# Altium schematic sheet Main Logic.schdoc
size 517 x 342 mm
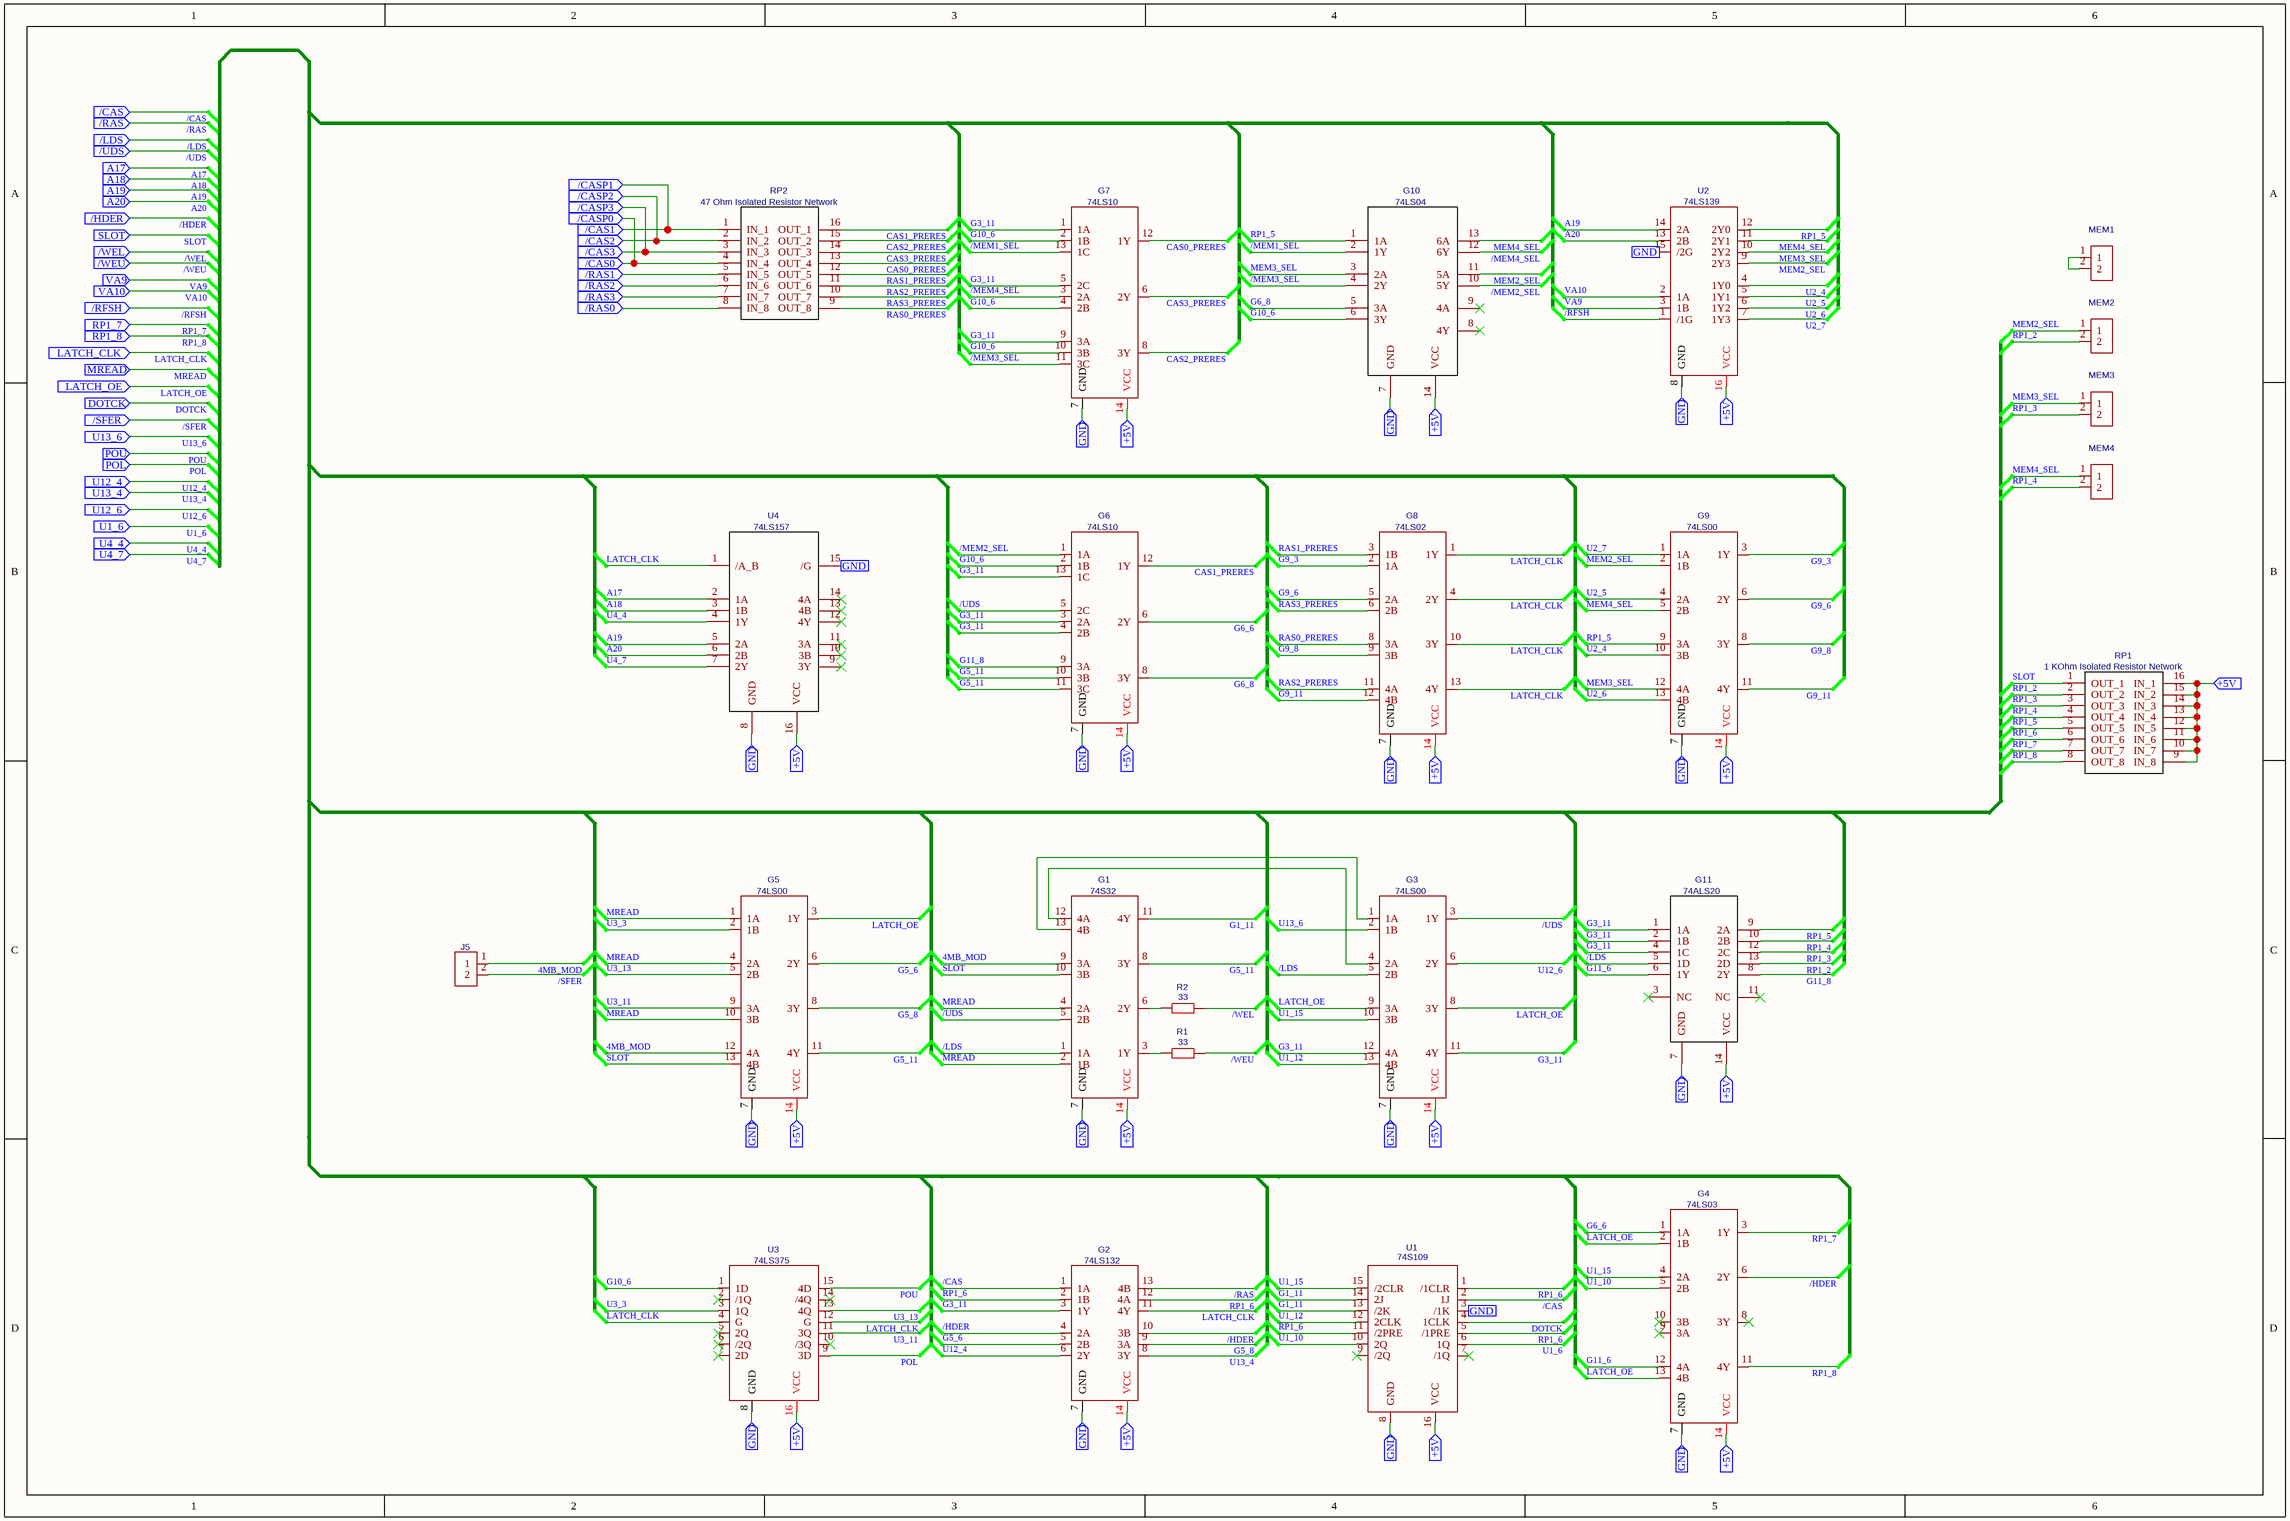
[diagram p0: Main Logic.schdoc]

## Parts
G1  74S32  [DIP-14_L19.4-W6.4-P2.54-LS7.6-BL]
G2  74LS132  [DIP-14_L19.2-W6.6-P2.54-LS10.9-BL]
G3  74LS00  [DIP14]
G4  74LS03  [DIP-14_L19.2-W6.6-P2.54-LS10.9-BL]
G5  74LS00  [DIP14]
G6  74LS10  [DIP14]
G7  74LS10  [DIP14]
G8  74LS02  [DIP-14_L19.4-W6.4-P2.54-LS7.6-BL]
G9  74LS00  [DIP14]
G10  74LS04  [DIP-14_L19.4-W6.4-P2.54-LS7.6-BL]
G11  74ALS20  [DIP-14_L19.4-W6.4-P2.54-LS7.6-BL]
J5  JUMPER2  [HDR-TH_2P-P2.54-V-M-1]  (value not drawn)
MEM1  MEM1  [HDR-TH_2P-P2.54-V-M-1]  (value not drawn)
MEM2  MEM2  [HDR-TH_2P-P2.54-V-M-1]  (value not drawn)
MEM3  MEM3  [HDR-TH_2P-P2.54-V-M-1]  (value not drawn)
MEM4  MEM4  [HDR-TH_2P-P2.54-V-M-1]  (value not drawn)
R1  33  [NARROW_RESISTOR]
R2  33  [NARROW_RESISTOR]
RP1  1 KOhm Isolated Resistor Network  [DIP-16_L19.7-W6.6-P2.54-LS7.6-BL]
RP2  47 Ohm Isolated Resistor Network  [DIP-16_L19.7-W6.6-P2.54-LS7.6-BL]
U1  74S109 (LISA)  [DIP-16_L19.7-W6.6-P2.54-LS7.6-BL]  (value not drawn)
U2  74LS139  [DIP-16_L19.7-W6.6-P2.54-LS7.6-BL]
U3  74LS375  [DIP-16_L19.7-W6.6-P2.54-LS7.6-BL]
U4  74LS157  [DIP-16_L19.7-W6.6-P2.54-LS7.6-BL]

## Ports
+5V (in), /CAS0 (in), /CAS1 (in), /CAS2 (in), /CAS3 (in), /CAS (in), /CASP0 (in), /CASP1 (in), /CASP2 (in), /CASP3 (in), /HDER (in), /LDS (in), /RAS0 (in), /RAS1 (in), /RAS2 (in), /RAS3 (in), /RAS (in), /RFSH (in), /SFER (in), /UDS (in), /WEL (in), /WEU (in), A17 (in), A18 (in), A19 (in), A20 (in), DOTCK (in), GND (in), LATCH_CLK (in), LATCH_OE (in), MREAD (in), POL (in), POU (in), RP1_7 (in), RP1_8 (in), SLOT (in), U1_6 (in), U4_4 (in), U4_7 (in), U12_4 (in), U12_6 (in), U13_4 (in), U13_6 (in), VA9 (in), VA10 (in)

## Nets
4MB_MOD: G1.9(3A) G5.12(4A) J5.1
+5V: G1.14(VCC) G2.14(VCC) G3.14(VCC) G4.14(VCC) G5.14(VCC) G6.14(VCC) G7.14(VCC) G8.14(VCC) G9.14(VCC) G10.14(VCC) G11.14(VCC) RP1.9(IN_8) RP1.10(IN_7) RP1.11(IN_6) RP1.12(IN_5) RP1.13(IN_4) RP1.14(IN_3) RP1.15(IN_2) RP1.16(IN_1) U1.16(VCC) U2.16(VCC) U3.16(VCC) U4.16(VCC) ; port +5V
/CAS: G2.1(1A) U1.2(1J) ; port /CAS
/CAS0: RP2.4(IN_4) ; port /CAS0, port /CASP0
/CAS1: RP2.1(IN_1) ; port /CAS1, port /CASP1
/CAS2: RP2.2(IN_2) ; port /CAS2, port /CASP2
/CAS3: RP2.3(IN_3) ; port /CAS3, port /CASP3
/HDER: G2.4(2A) G2.10(3B) G4.6(2Y) ; port /HDER
/LDS: G1.1(1A) G3.5(2B) G11.5(1D) ; port /LDS
/MEM1_SEL: G7.13(1C) G10.2(1Y)
/MEM2_SEL: G6.1(1A) G10.10(5Y)
/MEM3_SEL: G7.11(3C) G10.4(2Y)
/MEM4_SEL: G7.3(2A) G10.12(6Y)
/RAS: G2.13(4B) ; port /RAS
/RAS0: RP2.8(IN_8) ; port /RAS0
/RAS1: RP2.5(IN_5) ; port /RAS1
/RAS2: RP2.6(IN_6) ; port /RAS2
/RAS3: RP2.7(IN_7) ; port /RAS3
/RFSH: U2.1(/1G) ; port /RFSH
/SFER: J5.2 ; port /SFER
/UDS: G1.5(2B) G3.3(1Y) G6.5(2C) ; port /UDS
/WEL: R2.1 ; port /WEL
/WEU: R1.1 ; port /WEU
A17: U4.2(1A) ; port A17
A18: U4.3(1B) ; port A18
A19: U2.14(2A) U4.5(2A) ; port A19
A20: U2.13(2B) U4.6(2B) ; port A20
CAS0_PRERES: G7.12(1Y) RP2.13(OUT_4)
CAS1_PRERES: G6.12(1Y) RP2.16(OUT_1)
CAS2_PRERES: G7.8(3Y) RP2.15(OUT_2)
CAS3_PRERES: G7.6(2Y) RP2.14(OUT_3)
DOTCK: U1.4(1CLK) ; port DOTCK
G1_11: G1.11(4Y) U1.13(/2K) U1.14(2J)
G3_11: G2.3(1Y) G3.11(4Y) G3.12(4A) G6.3(2A) G6.4(2B) G6.13(1C) G7.1(1A) G7.5(2C) G7.9(3A) G11.1(1A) G11.2(1B) G11.4(1C)
G5_6: G2.5(2B) G5.6(2Y)
G5_8: G2.9(3A) G5.8(3Y)
G5_11: G1.8(3Y) G5.11(4Y) G6.10(3B) G6.11(3C)
G6_6: G4.1(1A) G6.6(2Y)
G6_8: G6.8(3Y) G10.5(3A)
G9_3: G8.2(1A) G9.3(1Y)
G9_6: G8.5(2A) G9.6(2Y)
G9_8: G8.9(3B) G9.8(3Y)
G9_11: G8.12(4B) G9.11(4Y)
G10_6: G6.2(1B) G7.2(1B) G7.4(2B) G7.10(3B) G10.6(3Y) U3.1(1D)
G11_6: G4.12(4A) G11.6(1Y)
G11_8: G6.9(3A) G11.8(2Y)
GND: G1.7(GND) G2.7(GND) G3.7(GND) G4.7(GND) G5.7(GND) G6.7(GND) G7.7(GND) G8.7(GND) G9.7(GND) G10.7(GND) G11.7(GND) U1.3(/1K) U1.8(GND) U2.8(GND) U2.15(/2G) U3.8(GND) U4.8(GND) U4.15(/G) ; port GND
LATCH_CLK: G2.11(4Y) G8.1(1Y) G8.4(2Y) G8.10(3Y) G8.13(4Y) U3.4(G) U3.12(G) U4.1(/A_B) ; port LATCH_CLK
LATCH_OE: G3.8(3Y) G3.9(3A) G4.2(1B) G4.13(4B) G5.3(1Y) ; port LATCH_OE
MEM2_SEL: G9.2(1B) G10.11(5A) MEM2.1 U2.9(2Y3)
MEM3_SEL: G9.12(4A) G10.3(2A) MEM3.1 U2.10(2Y2)
MEM4_SEL: G9.5(2B) G10.13(6A) MEM4.1 U2.11(2Y1)
MREAD: G1.2(1B) G1.4(2A) G5.1(1A) G5.4(2A) G5.10(3B) ; port MREAD
POL: U3.9(3D) ; port POL
POU: U3.15(4D) ; port POU
RAS0_PRERES: G8.8(3A) RP2.9(OUT_8)
RAS1_PRERES: G8.3(1B) RP2.12(OUT_5)
RAS2_PRERES: G8.11(4A) RP2.11(OUT_6)
RAS3_PRERES: G8.6(2B) RP2.10(OUT_7)
RP1_2: G11.13(2D) MEM2.2 RP1.2(OUT_2)
RP1_3: G11.12(2C) MEM3.2 RP1.3(OUT_3)
RP1_4: G11.10(2B) MEM4.2 RP1.4(OUT_4)
RP1_5: G9.9(3A) G10.1(1A) G11.9(2A) RP1.5(OUT_5) U2.12(2Y0)
RP1_6: G2.2(1B) G2.12(4A) RP1.6(OUT_6) U1.1(/1CLR) U1.5(/1PRE) U1.11(/2PRE)
RP1_7: G4.3(1Y) RP1.7(OUT_7) ; port RP1_7
RP1_8: G4.11(4Y) RP1.8(OUT_8) ; port RP1_8
SLOT: G1.10(3B) G5.13(4B) RP1.1(OUT_1) ; port SLOT
U1_6: U1.6(1Q) ; port U1_6
U1_10: G4.5(2B) U1.10(2Q)
U1_12: G3.13(4B) U1.12(2CLK)
U1_15: G3.10(3B) G4.4(2A) U1.15(/2CLR)
U2_4: G9.10(3B) U2.4(1Y0)
U2_5: G9.4(2A) U2.5(1Y1)
U2_6: G9.13(4B) U2.6(1Y2)
U2_7: G9.1(1A) U2.7(1Y3)
U3_3: G5.2(1B) U3.3(1Q)
U3_11: G5.9(3A) U3.11(3Q)
U3_13: G5.5(2B) U3.13(4Q)
U4_4: U4.4(1Y) ; port U4_4
U4_7: U4.7(2Y) ; port U4_7
U12_4: G2.6(2Y) ; port U12_4
U12_6: G3.6(2Y) ; port U12_6
U13_4: G2.8(3Y) ; port U13_4
U13_6: G3.2(1B) ; port U13_6
VA9: U2.3(1B) ; port VA9
VA10: U2.2(1A) ; port VA10
NetG1_3: G1.3(1Y) R1.2
NetG1_6: G1.6(2Y) R2.2
NetG1_12: G1.12(4A) G3.4(2A)
NetG1_13: G1.13(4B) G3.1(1A)
NetMEM1_1: MEM1.1 MEM1.2

Not connected (* = marked no-connect by the designer): G4 8(3Y)* 9(3A)* 10(3B)*; G10 8(4Y)* 9(4A)*; G11 3(NC)* 11(NC)*; U1 7(/1Q)* 9(/2Q)*; U3 2(/1Q)* 5(2Q)* 6(/2Q)* 7(2D)* 10(/3Q)* 14(/4Q)*; U4 9(3Y)* 10(3B)* 11(3A)* 12(4Y)* 13(4B)* 14(4A)*

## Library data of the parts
G1 = 74S32: Contributor: will_tooker
G2 = 74LS132: Contributor: will_tooker
G3 G5 G9 = 74LS00: Contributor: will_tooker
G4 = 74LS03: Contributor: William Tooker
G6 G7 = 74LS10: Contributor: will_tooker
G8 = 74LS02: Contributor: will_tooker
G10 = 74LS04: Contributor: William Tooker
G11 = 74ALS20: Contributor: will_tooker
J5 = JUMPER2: Manufacturer: null; Contributor: William Tooker
MEM1 = MEM1: Manufacturer: null; Manufacturer Part: Jumper2; Contributor: William Tooker
MEM2 = MEM2: Manufacturer: null; Manufacturer Part: Jumper2; Contributor: William Tooker
MEM3 = MEM3: Manufacturer: null; Manufacturer Part: Jumper2; Contributor: William Tooker
MEM4 = MEM4: Manufacturer: null; Manufacturer Part: Jumper2; Contributor: William Tooker
R1 R2 = 33: Manufacturer: YAGEO; Manufacturer Part: MFR-25JT-52-33R; nameAlias: Resistance (Ohms); Contributor: LCSC; Resistance: 33Ω
RP1 = 1 KOhm Isolated Resistor Network: Contributor: William Tooker
RP2 = 47 Ohm Isolated Resistor Network: Contributor: will_tooker
U1 = 74S109 (LISA): Contributor: William Tooker
U2 = 74LS139: Contributor: will_tooker
U3 = 74LS375: Contributor: William Tooker
U4 = 74LS157: Contributor: will_tooker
